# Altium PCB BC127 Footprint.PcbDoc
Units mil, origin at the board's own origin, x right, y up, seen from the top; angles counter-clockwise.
Board outline 6000 x 4000 mil, 2 copper layers (Top Layer, Bottom Layer); 1 components, 0 nets, 51 pads, 0 vias.
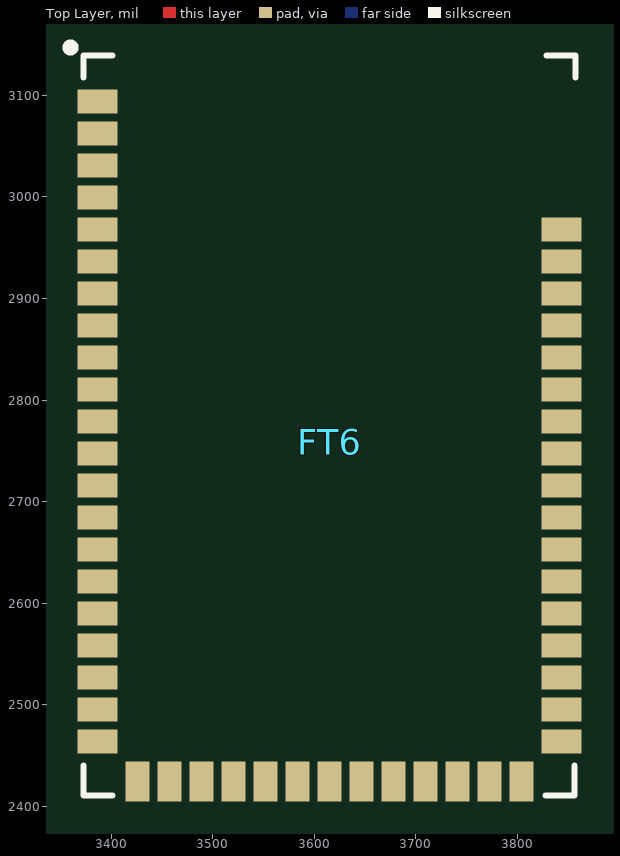
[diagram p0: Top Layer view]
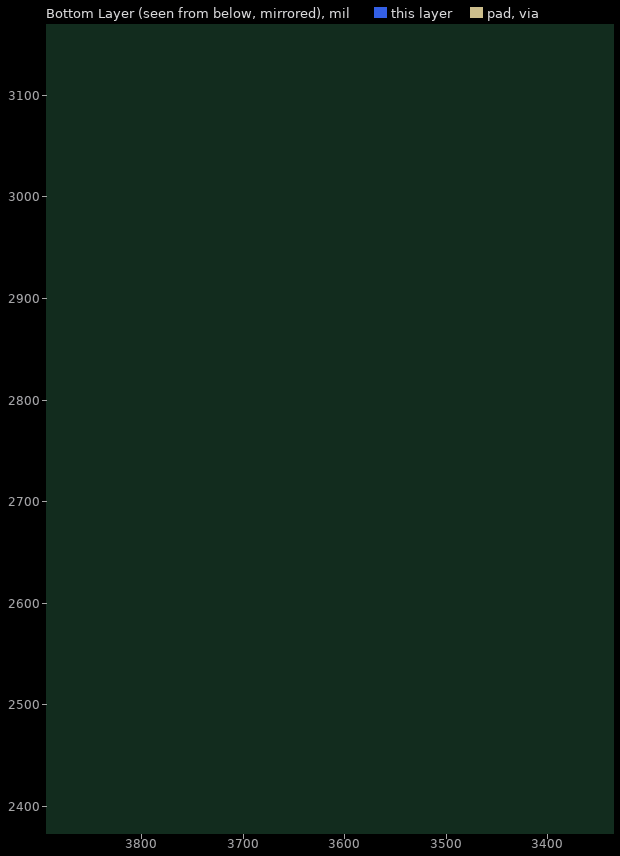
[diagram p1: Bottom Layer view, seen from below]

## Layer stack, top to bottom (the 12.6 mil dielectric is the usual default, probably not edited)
Top Solder: solder mask 0.4, Solder Resist, Dk 3.5
Top Layer: signal copper 1.4
Dielectric 1: dielectric 12.6, FR-4, Dk 4.8
Bottom Layer: signal copper 1.4
Bottom Solder: solder mask 0.4, Solder Resist, Dk 3.5

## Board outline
1000,1000 7000,1000 7000,5000 1000,5000

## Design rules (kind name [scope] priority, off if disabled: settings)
Clearance [All] p1: gap=10
PolygonConnect [All] p1: connectstyle=Relief reliefconductorwidth=10 reliefentries=4 polygonreliefangle="90 Angle" airgapwidth=10
RoutingVias [All] p1: holewidth=28 width=50 viastyle="Through Hole" minholewidth=28 minwidth=50 maxholewidth=28 maxwidth=50
SolderMaskExpansion [All] p1: expansion=4
Width [All] p1: maxlimit=10 minlimit=10 preferedwidth=10
29 further rules are at their usual default settings.

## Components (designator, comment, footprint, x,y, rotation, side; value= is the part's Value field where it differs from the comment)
FT6 "Comment" "LGA51 Blue Creation BC127" 3615,2775 r0 top

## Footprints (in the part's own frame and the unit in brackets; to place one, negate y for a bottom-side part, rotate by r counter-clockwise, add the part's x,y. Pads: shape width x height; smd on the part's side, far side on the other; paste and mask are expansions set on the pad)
"LGA51 Blue Creation BC127" [mm] "LGA, 51-Leads, Body 18x11.8mm, Pitch 0.8mm"
  rect 1x0.6 smd paste+0 mask+0.05: 1(-5.8,8.1) 2(-5.8,7.3) 3(-5.8,6.5) 4(-5.8,5.7) 5(-5.8,4.9) 6(-5.8,4.1) 7(-5.8,3.3) 8(-5.8,2.5) 9(-5.8,1.7) 10(-5.8,0.9) 11(-5.8,0.1) 12(-5.8,-0.7) 13(-5.8,-1.5) 14(-5.8,-2.3) 15(-5.8,-3.1) 16(-5.8,-3.9) 17(-5.8,-4.7) 18(-5.8,-5.5) 19(-5.8,-6.3) 20(-5.8,-7.1) 21(-5.8,-7.9) 35(5.8,-7.9) 36(5.8,-7.1) 37(5.8,-6.3) 38(5.8,-5.5) 39(5.8,-4.7) 40(5.8,-3.9) 41(5.8,-3.1) 42(5.8,-2.3) 43(5.8,-1.5) 44(5.8,-0.7) 45(5.8,0.1) 46(5.8,0.9) 47(5.8,1.7) 48(5.8,2.5) 49(5.8,3.3) 50(5.8,4.1) 51(5.8,4.9)
  rect 0.6x1 smd paste+0 mask+0.05: 22(-4.8,-8.9) 23(-4,-8.9) 24(-3.2,-8.9) 25(-2.4,-8.9) 26(-1.6,-8.9) 27(-0.8,-8.9) 28(0,-8.9) 29(0.8,-8.9) 30(1.6,-8.9) 31(2.4,-8.9) 32(3.2,-8.9) 33(4,-8.9) 34(4.8,-8.9)
  silkscreen extent -6.57,-9.25 6.15,9.55, body extent -5.9,-9 5.9,9, height 2.4

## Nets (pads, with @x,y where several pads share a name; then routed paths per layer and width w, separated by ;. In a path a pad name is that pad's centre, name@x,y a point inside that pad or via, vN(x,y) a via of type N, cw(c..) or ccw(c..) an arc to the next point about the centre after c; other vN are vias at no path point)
pads on no net: FT6.1 FT6.2 FT6.3 FT6.4 FT6.5 FT6.6 FT6.7 FT6.8 FT6.9 FT6.10 FT6.11 FT6.12 FT6.13 FT6.14 FT6.15 FT6.16 FT6.17 FT6.18 FT6.19 FT6.20 FT6.21 FT6.22 FT6.23 FT6.24 FT6.25 FT6.26 FT6.27 FT6.28 FT6.29 FT6.30 FT6.31 FT6.32 FT6.33 FT6.34 FT6.35 FT6.36 FT6.37 FT6.38 FT6.39 FT6.40 FT6.41 FT6.42 FT6.43 FT6.44 FT6.45 FT6.46 FT6.47 FT6.48 FT6.49 FT6.50 FT6.51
